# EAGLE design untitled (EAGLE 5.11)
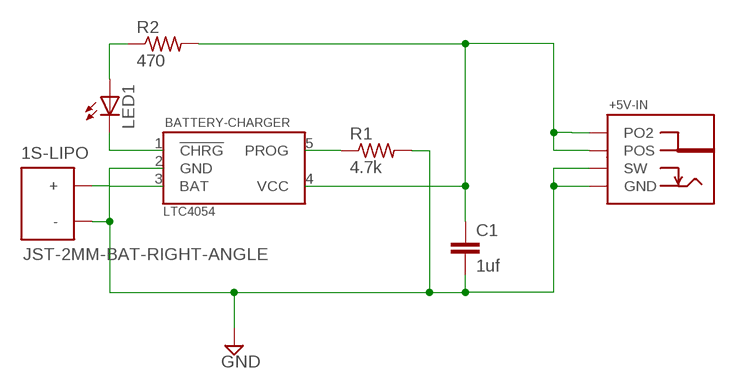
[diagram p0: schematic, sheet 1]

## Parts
1S-LIPO  JST-2MM-BAT-RIGHT-ANGLE  [JST-2MM-BAT-RIGHT-ANGLE]
+5V-IN  POWER-JACK-3.5MM-1.3MM-SMD-SW  [POWER-JACK-3.5MM-1.3MM-SMD-SW]
BATTERY-CHARGER  LTC4054  [TSOT23-5]
C1  1uf  C-EUC1206  [C1206]
LED1  LED3MM  [LED3MM]
R1  4.7k  R-US_R1206  [R1206]
R2  470  R-US_R1206  [R1206]

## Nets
GND: 1S-LIPO.2(-) +5V-IN.2(GND) +5V-IN.3(SW) BATTERY-CHARGER.2(GND) C1.2 R1.2
N$1: 1S-LIPO.1(+) BATTERY-CHARGER.3(BAT)
N$2: BATTERY-CHARGER.5(PROG) R1.1
N$3: BATTERY-CHARGER.1(!CHRG) LED1.K(C)
N$4: LED1.A R2.1
N$5: +5V-IN.1A(POS) +5V-IN.1B(PO2) BATTERY-CHARGER.4(VCC) C1.1 R2.2

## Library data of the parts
1S-LIPO = trl:JST-2MM-BAT-RIGHT-ANGLE
+5V-IN = trl:POWER-JACK-3.5MM-1.3MM-SMD-SW
BATTERY-CHARGER = trl:LTC4054
C1 = rcl:C-EU: CAPACITOR, European symbol
LED1 = led:LED: LED
R1 R2 = resistor:R-US_: RESISTOR, American symbol

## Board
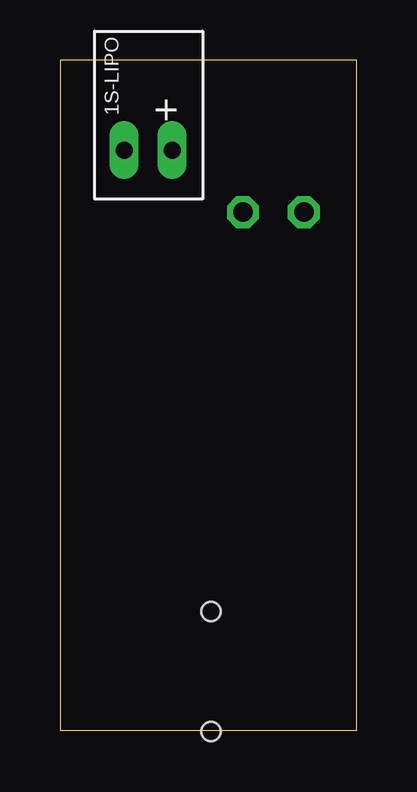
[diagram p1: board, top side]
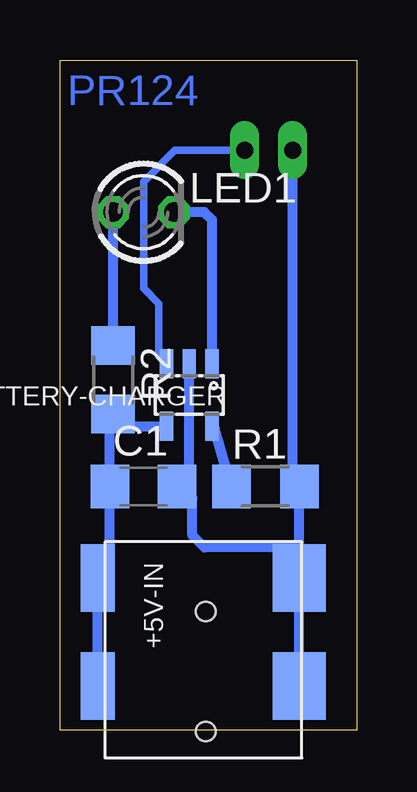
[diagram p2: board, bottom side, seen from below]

Size 12.37 x 27.93 mm. Coordinates in mm from the lower left corner, seen from the top.
Outline: 0,0 12.37,0 12.37,27.93 0,27.93 0,0
Copper layers (1*16): Top 0.035mm / dielectric 1.5mm / Bottom 0.035mm
Design rules "default": minimum track width 10mil, minimum drill 24mil, track to track 8mil, track to pad 8mil, pad to pad 8mil, via to via 8mil, smd to smd 8mil, copper to edge 40mil, drill to drill 8mil, minimum pad ring 10mil, minimum via ring 8mil, stop-mask expansion 4mil, vias tented up to drill 0mil, thermal gap 10mil

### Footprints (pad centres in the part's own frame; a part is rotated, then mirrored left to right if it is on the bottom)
JST-2MM-BAT-RIGHT-ANGLE = drill 0.7 pad 1.016 long: 1 -2.5,-1.5; 2 -2.5,0.5
POWER-JACK-3.5MM-1.3MM-SMD-SW = smd 2.8 x 1.4: 1A -3.81,-3.81; 1B 0.69,-3.81 | smd 2.8 x 2.2: 2 0.69,4.59; 3 -3.81,4.59 | hole 0.8: -2.41,0.69; 2.59,0.69
TSOT23-5 = smd 0.55 x 1.2: 1 -0.95,-1.3; 2 0,-1.3; 3 0.95,-1.3; 4 0.95,1.3; 5 -0.95,1.3
C1206 = smd 1.6 x 1.8: 1 -1.4,0; 2 1.4,0
LED3MM = drill 0.813 octagon: A -1.27,0; K 1.27,0
R1206 = smd 1.6 x 1.803: 1 -1.422,0; 2 1.422,0

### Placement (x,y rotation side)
1S-LIPO  3.17,26.67 90 top
+5V-IN  6.99,2.54 270 bottom
BATTERY-CHARGER  6.99,13.97 180 bottom
C1  8.89,10.16 0 bottom
LED1  8.89,21.59 0 bottom
R1  3.81,10.16 0 bottom
R2  10.16,14.61 270 bottom

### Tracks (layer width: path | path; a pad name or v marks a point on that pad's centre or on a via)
GND
  Bottom 0.406: 6.86,9.65 C1.2 | 6.86,9.65 6.99,10.79 BATTERY-CHARGER.2 | +5V-IN.2 +5V-IN.3 2.4,7.62 | 2.4,7.62 R1.2 2.67,10.45 1S-LIPO.2 | 6.86,9.65 6.86,8.12 6.35,7.62 2.4,7.62
N$1
  Bottom 0.305: 1S-LIPO.1 7.58,24.17 7.62,24.13 8.89,22.86 8.89,19.05 8.89,18.41 8.26,17.78 8.26,15.59 BATTERY-CHARGER.3
N$2
  Bottom 0.406: R1.1 5.91,12.55 BATTERY-CHARGER.5
N$3
  Bottom 0.406: BATTERY-CHARGER.1 6.04,21.27 6.35,21.59 LED1.K
N$4
  Bottom 0.406: R2.1 10.16,17.56 LED1.A
N$5
  Bottom 0.305: R2.2 10.29,13.05 10.29,12.7 10.26,12.67
  Bottom 0.406: +5V-IN.1B +5V-IN.1A 10.29,7.49 C1.1 10.29,12.7 | 10.26,12.67 BATTERY-CHARGER.4

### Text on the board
Bottom: PR124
